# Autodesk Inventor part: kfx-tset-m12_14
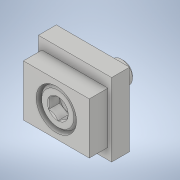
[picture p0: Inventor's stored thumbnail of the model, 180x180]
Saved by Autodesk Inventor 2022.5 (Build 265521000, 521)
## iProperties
Created: 2021-10
Part Number: kfx-tset-m12_14
Material: 一般
Document SubType Name: Modeling
Designer: ImaoCorp
Density: 1 g/cm^3
Appearance: 既定
Author: ImaoCorp
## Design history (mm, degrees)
feature "kfx-tset-m12_14"
node "ソリッド1"
